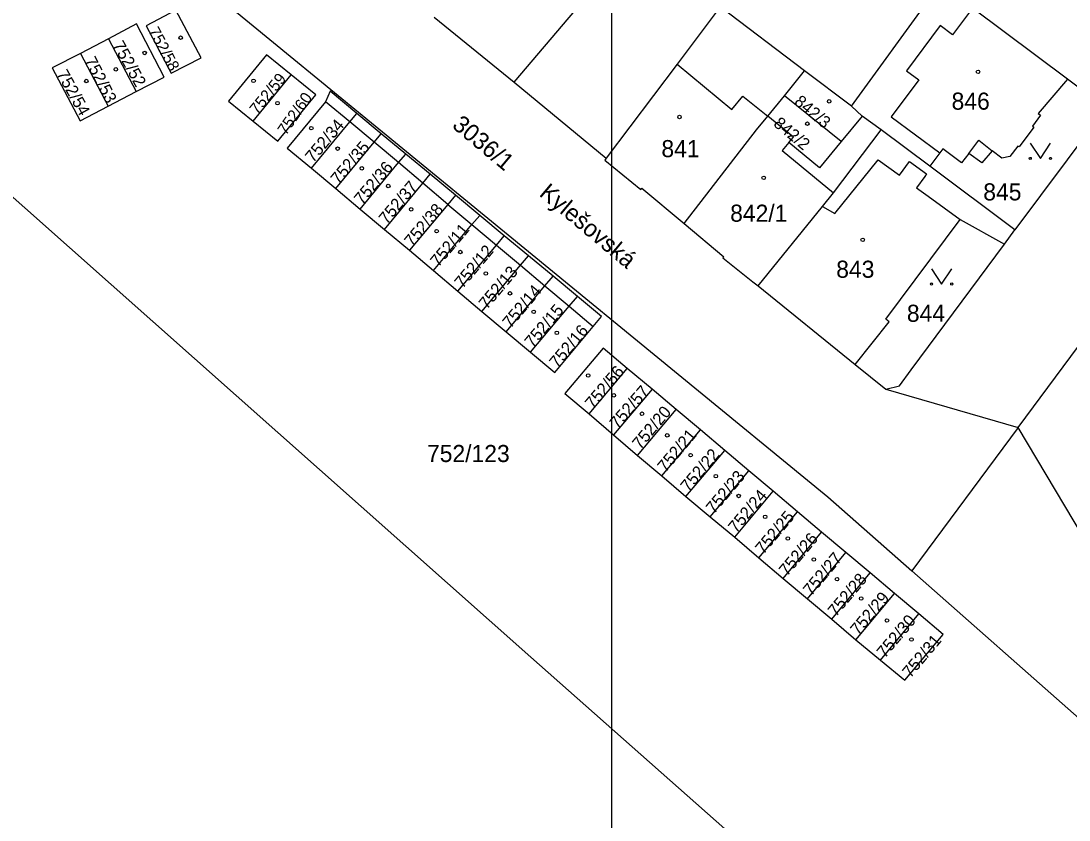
# Model space of a CAD drawing. Extents: x -496682 to -495907, y -1088575 to -1088018.
# Drawn here: x -496196 to -496091.9, y -1088386.2 to -1088306.8 of the extents above; entities that cross this region are included whole.
import ezdxf

# ---------------------------------------------------------------- set-up
doc = ezdxf.new("R2010")
doc.units = 0
for name, color, linetype in [('Hranice parcel', 7, 'Continuous'), ('Parcelní čísla', 7, 'Continuous'), ('Pop  PČ popisy', 7, 'Continuous'), ('Vnitřní kresba', 7, 'Continuous'), ('Vrstva 63', 7, 'Continuous'), ('Značky budov', 7, 'Continuous'), ('Značky kultur', 7, 'Continuous')]:
    doc.layers.add(name, color=color, linetype=linetype)

msp = doc.modelspace()

# ---------------------------------------------------------------- linework, layer by layer
at = {"layer": 'Hranice parcel'}
for p, q in [((-496113.5, -1088315.25), (-496104.68, -1088303.11)), ((-496118.15, -1088311.73), (-496126.53, -1088305.37)), ((-496154.95, -1088306.41), (-496147.01, -1088312.86)), ((-496187.32, -1088308.54), (-496190.11, -1088310)), ((-496187.32, -1088308.54), (-496184.56, -1088313.8)), ((-496190.11, -1088310), (-496187.36, -1088315.26)), ((-496172.94, -1088316.74), (-496169.17, -1088312.12)), ((-496120.16, -1088314.21), (-496118.15, -1088311.73)), ((-496113.5, -1088315.25), (-496118.15, -1088311.73)), ((-496147.01, -1088312.86), (-496137.88, -1088320.43)), ((-496088.23, -1088315.43), (-496092.02, -1088312.57)), ((-496187.36, -1088315.26), (-496184.56, -1088313.8)), ((-496121.81, -1088316.24), (-496120.16, -1088314.21)), ((-496114.51, -1088318.76), (-496120.16, -1088314.21)), ((-496112.44, -1088316.23), (-496113.5, -1088315.25)), ((-496088.23, -1088315.43), (-496097.26, -1088327.56)), ((-496160.21, -1088317.99), (-496162.63, -1088315.98)), ((-496112.44, -1088316.23), (-496114.51, -1088318.76)), ((-496110.54, -1088317.61), (-496112.44, -1088316.23)), ((-496105.72, -1088321.22), (-496110.54, -1088317.61)), ((-496157.78, -1088320.01), (-496160.21, -1088317.99)), ((-496096.94, -1088347.2), (-496075.94, -1088318.85)), ((-496155.35, -1088322.02), (-496157.78, -1088320.01)), ((-496167.15, -1088321.43), (-496164.73, -1088323.45)), ((-496097.26, -1088327.56), (-496105.72, -1088321.22)), ((-496152.84, -1088324.11), (-496155.35, -1088322.02)), ((-496164.73, -1088323.45), (-496162.32, -1088325.48)), ((-496150.42, -1088326.11), (-496152.84, -1088324.11)), ((-496162.32, -1088325.48), (-496159.9, -1088327.5)), ((-496122.78, -1088333.12), (-496116.38, -1088325.22)), ((-496147.99, -1088328.13), (-496150.42, -1088326.11)), ((-496159.9, -1088327.5), (-496157.42, -1088329.57)), ((-496098.3, -1088328.96), (-496097.26, -1088327.56)), ((-496145.58, -1088330.13), (-496147.99, -1088328.13)), ((-496157.42, -1088329.57), (-496155.02, -1088331.59)), ((-496143.15, -1088332.15), (-496145.58, -1088330.13)), ((-496155.02, -1088331.59), (-496152.6, -1088333.64)), ((-496140.72, -1088334.17), (-496143.15, -1088332.15)), ((-496123.28, -1088332.72), (-496122.78, -1088333.12)), ((-496122.78, -1088333.12), (-496113.14, -1088340.92)), ((-496152.6, -1088333.64), (-496150.21, -1088335.65)), ((-496150.21, -1088335.65), (-496147.79, -1088337.68)), ((-496147.79, -1088337.68), (-496145.37, -1088339.71)), ((-496139.57, -1088345.84), (-496135.78, -1088341.33)), ((-496133.31, -1088343.39), (-496135.78, -1088341.33)), ((-496113.14, -1088340.92), (-496110.08, -1088343.39)), ((-496133.31, -1088343.39), (-496137.13, -1088347.93)), ((-496130.91, -1088345.41), (-496133.31, -1088343.39)), ((-496110.08, -1088343.39), (-496096.94, -1088347.2)), ((-496134.74, -1088349.98), (-496130.91, -1088345.41)), ((-496128.5, -1088347.44), (-496130.91, -1088345.41)), ((-496139.57, -1088345.84), (-496137.13, -1088347.93)), ((-496132.33, -1088352.01), (-496128.5, -1088347.44)), ((-496126.09, -1088349.48), (-496128.5, -1088347.44)), ((-496096.94, -1088347.2), (-496107.5, -1088361.45)), ((-496078.26, -1088378.65), (-496096.94, -1088347.2)), ((-496137.13, -1088347.93), (-496134.74, -1088349.98)), ((-496129.94, -1088354.04), (-496126.09, -1088349.48)), ((-496123.68, -1088351.51), (-496126.09, -1088349.48)), ((-496134.74, -1088349.98), (-496132.33, -1088352.01)), ((-496132.33, -1088352.01), (-496129.94, -1088354.04)), ((-496127.52, -1088356.07), (-496123.68, -1088351.51)), ((-496121.27, -1088353.54), (-496123.68, -1088351.51)), ((-496129.94, -1088354.04), (-496127.52, -1088356.07)), ((-496125.1, -1088358.11), (-496121.27, -1088353.54)), ((-496118.87, -1088355.57), (-496121.27, -1088353.54)), ((-496127.52, -1088356.07), (-496125.1, -1088358.11)), ((-496122.69, -1088360.15), (-496118.87, -1088355.57)), ((-496116.46, -1088357.6), (-496118.87, -1088355.57)), ((-496125.1, -1088358.11), (-496122.69, -1088360.15)), ((-496120.28, -1088362.2), (-496116.46, -1088357.6)), ((-496114.05, -1088359.63), (-496116.46, -1088357.6)), ((-496122.69, -1088360.15), (-496120.28, -1088362.2)), ((-496117.87, -1088364.23), (-496114.05, -1088359.63)), ((-496111.64, -1088361.66), (-496114.05, -1088359.63)), ((-496120.28, -1088362.2), (-496117.87, -1088364.23)), ((-496115.45, -1088366.26), (-496111.64, -1088361.66)), ((-496109.23, -1088363.69), (-496111.64, -1088361.66)), ((-496117.87, -1088364.23), (-496115.45, -1088366.26)), ((-496113.05, -1088368.31), (-496109.23, -1088363.69)), ((-496106.81, -1088365.73), (-496109.23, -1088363.69)), ((-496115.45, -1088366.26), (-496113.05, -1088368.31)), ((-496110.62, -1088370.34), (-496106.81, -1088365.73)), ((-496113.05, -1088368.31), (-496110.62, -1088370.34))]:
    msp.add_line(p, q, dxfattribs=at)
for points in [[(-496188.02, -1088275.91), (-496175.34, -1088305.32), (-496115.85, -1088354.08), (-496107.5, -1088361.45)], [(-496147.01, -1088312.86), (-496138.54, -1088302.87), (-496133.98, -1088296.93)], [(-496092.02, -1088312.57), (-496101.47, -1088305.51), (-496104.68, -1088303.11)], [(-496181.09, -1088311.98), (-496178.12, -1088310.44), (-496180.61, -1088305.71), (-496183.56, -1088307.26), (-496181.09, -1088311.98)], [(-496126.53, -1088305.37), (-496130.83, -1088311.08), (-496137.88, -1088320.43)], [(-496184.56, -1088313.8), (-496181.77, -1088312.35), (-496184.53, -1088307.08), (-496187.32, -1088308.54)], [(-496190.11, -1088310), (-496192.9, -1088311.45), (-496190.14, -1088316.71), (-496187.36, -1088315.26)], [(-496169.17, -1088312.12), (-496171.6, -1088310.15), (-496175.38, -1088314.74), (-496172.94, -1088316.74)], [(-496172.94, -1088316.74), (-496170.5, -1088318.73), (-496166.73, -1088314.13), (-496169.17, -1088312.12)], [(-496092.02, -1088312.57), (-496094.95, -1088315.97), (-496094.7, -1088316.16), (-496095.5, -1088317.24), (-496095.38, -1088317.33), (-496096.85, -1088319.3), (-496096.97, -1088319.21), (-496097.76, -1088320.27), (-496098.57, -1088320.43), (-496099.52, -1088319.68)], [(-496085.86, -1088384.22), (-496089.4, -1088386.33), (-496106.83, -1088404.69), (-496113.8, -1088398.15), (-496126.07, -1088387.1), (-496145.34, -1088370.03), (-496208.08, -1088314.32), (-496232.37, -1088317.97)], [(-496162.63, -1088315.98), (-496165.3, -1088313.76), (-496165.75, -1088314.82), (-496169.56, -1088319.42), (-496167.15, -1088321.43)], [(-496167.15, -1088321.43), (-496163.33, -1088316.82), (-496162.63, -1088315.98)], [(-496130.12, -1088326.92), (-496122.92, -1088317.59), (-496121.81, -1088316.24)], [(-496114.51, -1088318.76), (-496116.67, -1088321.39), (-496119.73, -1088318.87), (-496119.27, -1088318.32), (-496121.81, -1088316.24)], [(-496116.38, -1088325.22), (-496115.28, -1088323.86), (-496110.54, -1088317.61)], [(-496164.73, -1088323.45), (-496160.91, -1088318.84), (-496160.21, -1088317.99)], [(-496102.56, -1088320.89), (-496104.41, -1088319.49), (-496104.72, -1088319.89), (-496105.72, -1088321.22)], [(-496099.52, -1088319.68), (-496100.53, -1088320.88), (-496101.83, -1088319.94), (-496102.56, -1088320.89)], [(-496162.32, -1088325.48), (-496158.49, -1088320.86), (-496157.78, -1088320.01)], [(-496137.88, -1088320.43), (-496138.01, -1088320.62), (-496134.44, -1088323.53), (-496134.33, -1088323.4), (-496130.12, -1088326.92)], [(-496159.9, -1088327.5), (-496156.07, -1088322.89), (-496155.35, -1088322.02)], [(-496152.84, -1088324.11), (-496153.6, -1088325.01), (-496157.42, -1088329.57)], [(-496155.02, -1088331.59), (-496151.21, -1088327.02), (-496150.42, -1088326.11)], [(-496130.12, -1088326.92), (-496126.19, -1088330.23), (-496126.29, -1088330.34), (-496123.28, -1088332.72)], [(-496113.14, -1088340.92), (-496109.74, -1088336.7), (-496110.07, -1088336.41), (-496102.69, -1088326.52), (-496098.3, -1088328.96)], [(-496152.6, -1088333.64), (-496148.78, -1088329.06), (-496147.99, -1088328.13)], [(-496110.08, -1088343.39), (-496108.73, -1088343.04), (-496107.57, -1088341.47), (-496098.3, -1088328.96)], [(-496150.21, -1088335.65), (-496146.38, -1088331.07), (-496145.58, -1088330.13)], [(-496147.79, -1088337.68), (-496143.97, -1088333.1), (-496143.15, -1088332.15)], [(-496145.37, -1088339.71), (-496141.55, -1088335.13), (-496140.72, -1088334.17)], [(-496145.37, -1088339.71), (-496142.97, -1088341.74), (-496139.15, -1088337.15), (-496138.32, -1088336.17), (-496140.72, -1088334.17)], [(-496135.78, -1088341.33), (-496138.17, -1088339.3), (-496141.97, -1088343.81), (-496139.57, -1088345.84)], [(-496107.5, -1088361.45), (-496090.31, -1088376.63), (-496085.86, -1088384.22)], [(-496110.62, -1088370.34), (-496108.2, -1088372.33), (-496104.4, -1088367.76), (-496106.81, -1088365.73)]]:
    msp.add_lwpolyline(points, dxfattribs=at)
at = {"layer": 'Vnitřní kresba'}
for p, q in [((-496101.47, -1088305.51), (-496103.46, -1088308.16)), ((-496104.69, -1088307.24), (-496108.02, -1088311.73)), ((-496103.46, -1088308.16), (-496104.69, -1088307.24)), ((-496130.83, -1088311.08), (-496125.37, -1088315.57)), ((-496108.02, -1088311.73), (-496106.81, -1088312.63)), ((-496106.81, -1088312.63), (-496109.56, -1088316.31)), ((-496125.37, -1088315.57), (-496124.3, -1088314.26)), ((-496124.3, -1088314.26), (-496121.81, -1088316.24)), ((-496163.33, -1088316.82), (-496165.75, -1088314.82)), ((-496109.56, -1088316.31), (-496104.72, -1088319.89)), ((-496160.91, -1088318.84), (-496163.33, -1088316.82)), ((-496101.83, -1088319.94), (-496100.85, -1088318.64)), ((-496100.85, -1088318.64), (-496099.52, -1088319.68)), ((-496158.49, -1088320.86), (-496160.91, -1088318.84)), ((-496119.73, -1088318.87), (-496120.38, -1088319.67)), ((-496120.38, -1088319.67), (-496115.28, -1088323.86)), ((-496115.16, -1088325.93), (-496110.83, -1088320.6)), ((-496110.83, -1088320.6), (-496108.74, -1088322.12)), ((-496108.74, -1088322.12), (-496107.74, -1088320.75)), ((-496107.74, -1088320.75), (-496106.03, -1088321.99)), ((-496156.07, -1088322.89), (-496158.49, -1088320.86)), ((-496106.21, -1088322.23), (-496107.03, -1088323.37)), ((-496106.03, -1088321.99), (-496106.21, -1088322.23)), ((-496153.6, -1088325.01), (-496156.07, -1088322.89)), ((-496107.03, -1088323.37), (-496105.88, -1088324.2)), ((-496105.88, -1088324.2), (-496102.69, -1088326.52)), ((-496153.6, -1088325.01), (-496151.21, -1088327.02)), ((-496116.38, -1088325.22), (-496115.16, -1088325.93)), ((-496151.21, -1088327.02), (-496148.78, -1088329.06)), ((-496148.78, -1088329.06), (-496146.38, -1088331.07)), ((-496146.38, -1088331.07), (-496143.97, -1088333.1)), ((-496143.97, -1088333.1), (-496141.55, -1088335.13)), ((-496141.55, -1088335.13), (-496139.15, -1088337.15))]:
    msp.add_line(p, q, dxfattribs=at)
at = {"layer": 'Vrstva 63'}
msp.add_lwpolyline([(-496137.35, -1088164.24), (-496137.35, -1088461.24), (-496557.35, -1088461.24), (-496557.35, -1088164.24)], close=True, dxfattribs=at)
at = {"layer": 'Značky budov'}
for centre in [(-496180.15, -1088308.44), (-496183.72, -1088309.96), (-496186.58, -1088311.59), (-496100.92, -1088311.84), (-496189.52, -1088312.75), (-496172.9, -1088312.73), (-496170.53, -1088314.95), (-496115.71, -1088314.77), (-496130.58, -1088316.33), (-496167.17, -1088317.44), (-496117.88, -1088316.99), (-496164.55, -1088319.47), (-496162.14, -1088321.43), (-496122.22, -1088322.38), (-496159.52, -1088323.19), (-496157.24, -1088325.5), (-496154.71, -1088327.67), (-496112.38, -1088328.54), (-496152.35, -1088329.75), (-496149.83, -1088331.88), (-496147.42, -1088333.86), (-496145.07, -1088335.69), (-496142.77, -1088337.78), (-496139.65, -1088342.02), (-496137.1, -1088344), (-496134.31, -1088345.83), (-496131.8, -1088347.98), (-496129.48, -1088349.95), (-496126.97, -1088352.03), (-496124.71, -1088354), (-496122.07, -1088356.08), (-496119.82, -1088358.23), (-496117.24, -1088360.32), (-496114.93, -1088362.28), (-496112.54, -1088364.19), (-496109.97, -1088366.39), (-496107.54, -1088368.28)]:
    msp.add_circle(centre, 0.175, dxfattribs=at)
at = {"layer": 'Značky kultur'}
for points in [[(-496095.73, -1088318.94), (-496094.73, -1088320.44), (-496093.73, -1088318.94)], [(-496105.54, -1088331.43), (-496104.54, -1088332.93), (-496103.54, -1088331.43)]]:
    msp.add_lwpolyline(points, dxfattribs=at)
for centre in [(-496095.73, -1088320.44), (-496093.73, -1088320.44), (-496105.54, -1088332.93), (-496103.54, -1088332.93)]:
    msp.add_circle(centre, 0.1, dxfattribs=at)

# ---------------------------------------------------------------- texts
at = {"layer": 'Parcelní čísla'}
for s, height, rotation, p in [('752/58', 1.139, 298, (-496183.39, -1088307.76)), ('752/52', 1.2, 299, (-496186.94, -1088309.17)), ('752/53', 1.2, 297, (-496189.73, -1088310.7)), ('752/54', 1.2, 299, (-496192.51, -1088312.03)), ('752/59', 1.139, 51, (-496172.52, -1088316.17)), ('752/60', 1.139, 55, (-496169.68, -1088318.21)), ('842/3', 1.2, 320, (-496119.27, -1088314.96)), ('752/34', 1.2, 50, (-496166.97, -1088320.94)), ('3036/1', 1.7, 320, (-496153.27, -1088317.31)), ('842/2', 1.2, 320, (-496121.33, -1088317.13)), ('752/35', 1.2, 50, (-496164.44, -1088323.13)), ('752/36', 1.2, 50, (-496162.11, -1088325.13)), ('752/37', 1.2, 50, (-496159.66, -1088327.08)), ('752/38', 1.2, 50, (-496157.12, -1088329.32)), ('752/11', 1.2, 50, (-496154.54, -1088331.31)), ('752/12', 1.2, 50, (-496152.13, -1088333.44)), ('752/13', 1.2, 50, (-496149.72, -1088335.53)), ('752/14', 1.2, 50, (-496147.37, -1088337.41)), ('752/15', 1.2, 50, (-496145.17, -1088339.34)), ('752/16', 1.2, 50, (-496142.71, -1088341.37)), ('752/56', 1.203, 50, (-496139.16, -1088345.45)), ('752/57', 1.213, 49, (-496136.73, -1088347.43)), ('752/20', 1.2, 50, (-496134.48, -1088349.46)), ('752/21', 1.2, 50, (-496131.97, -1088351.73)), ('752/22', 1.2, 50, (-496129.68, -1088353.69)), ('752/23', 1.2, 50, (-496127.16, -1088355.86)), ('752/24', 1.2, 50, (-496124.94, -1088357.76)), ('752/25', 1.2, 50, (-496122.25, -1088359.88)), ('752/26', 1.2, 50, (-496119.9, -1088362.05)), ('752/27', 1.2, 50, (-496117.5, -1088364.01)), ('752/28', 1.2, 50, (-496115.04, -1088366.08)), ('752/29', 1.2, 50, (-496112.81, -1088367.94)), ('752/30', 1.2, 50, (-496110.18, -1088370.2)), ('752/31', 1.2, 50, (-496107.64, -1088372.17))]:
    msp.add_text(s, height=height, rotation=rotation, dxfattribs=at).set_placement(p)
for s, p in [('846', (-496103.55, -1088315.6)), ('841', (-496132.38, -1088320.32)), ('845', (-496100.4, -1088324.62)), ('842/1', (-496125.55, -1088326.74)), ('843', (-496115.01, -1088332.31)), ('844', (-496107.99, -1088336.69)), ('752/123', (-496155.67, -1088350.63))]:
    msp.add_text(s, height=1.7, dxfattribs=at).set_placement(p)
at = {"layer": 'Pop  PČ popisy'}
msp.add_text('Kylešovská', height=1.7, rotation=320, dxfattribs=at).set_placement((-496144.61, -1088324.09))

doc.saveas('drawing.dxf')
